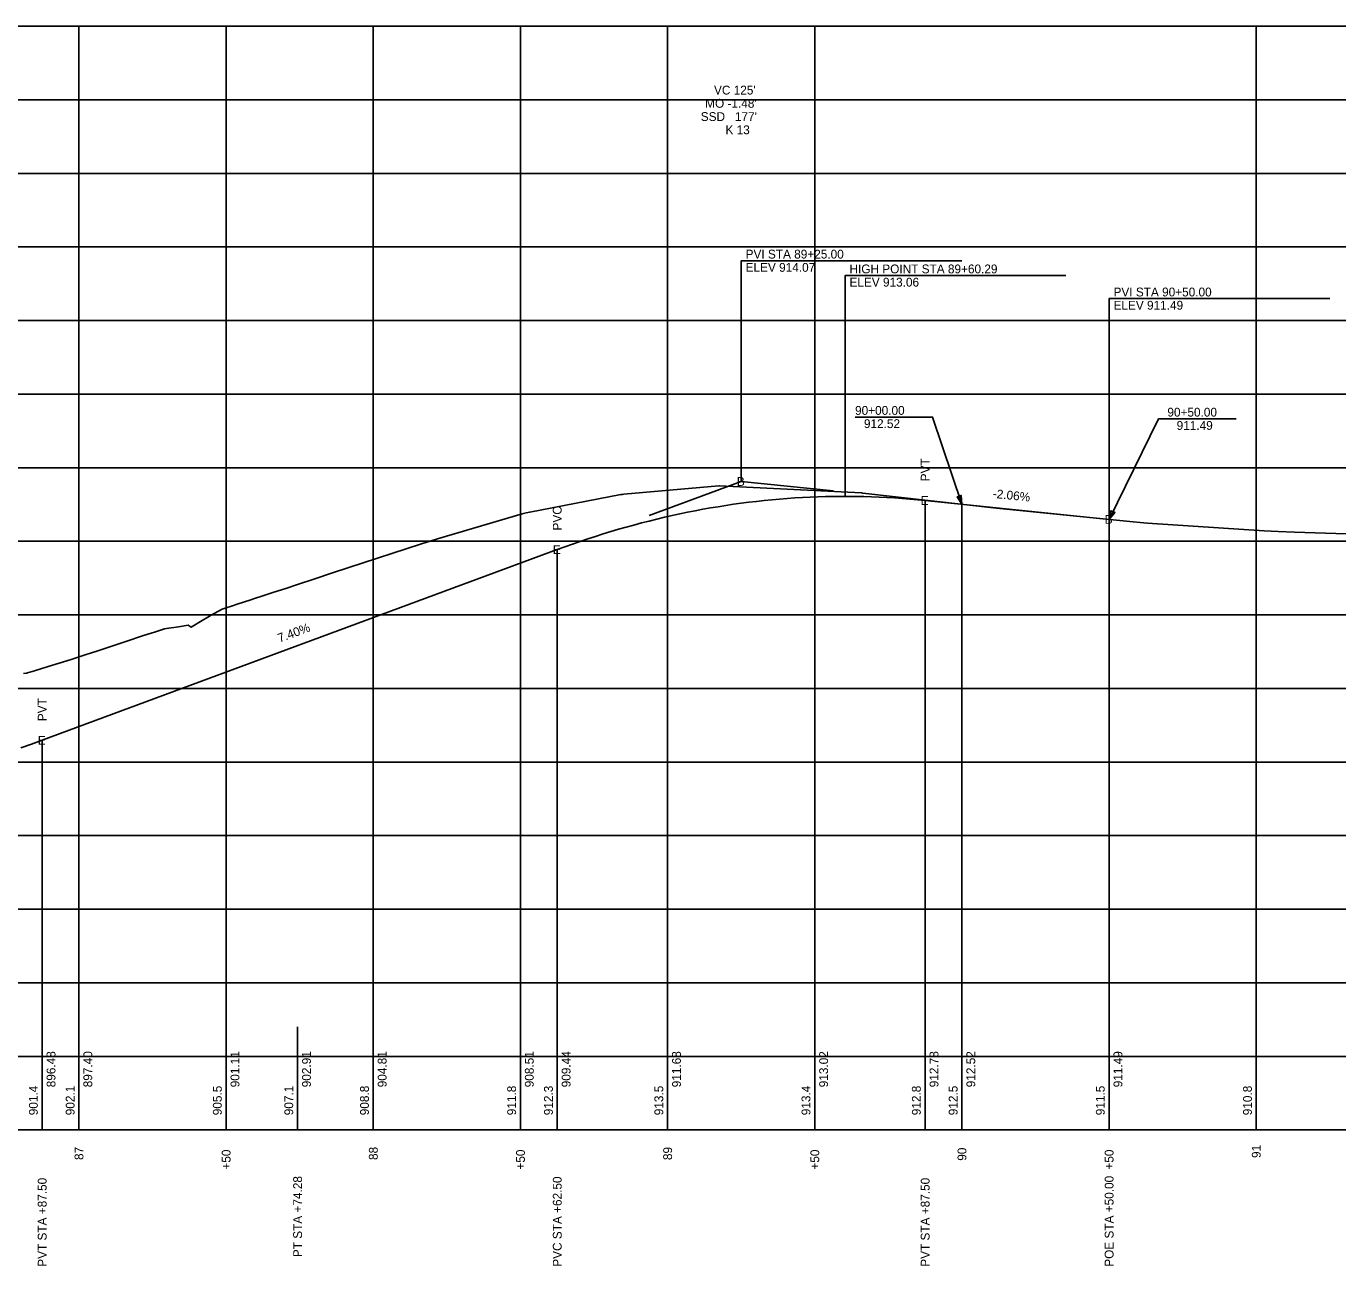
# Model space of a CAD drawing. Extents: x 76292 to 78417, y 50412 to 52585.
# Drawn here: x 77087.4 to 77533, y 51114.2 to 51535.3 of the extents above; entities that cross this region are included whole.
import ezdxf

# ---------------------------------------------------------------- set-up
doc = ezdxf.new("R2010")
doc.units = 0
for name, color, linetype in [('1', 7, 'Continuous'), ('2', 7, 'Continuous'), ('3', 7, 'Continuous'), ('32', 7, 'Continuous'), ('33', 7, 'Continuous'), ('63', 7, 'Continuous'), ('Default', 7, 'Continuous')]:
    doc.layers.add(name, color=color, linetype=linetype)

msp = doc.modelspace()

# ---------------------------------------------------------------- linework, layer by layer
at = {"layer": '1'}
for p, q in [((76305.34, 51160.35), (78405.34, 51160.35)), ((77105.34, 51160.35), (77105.34, 51160.35)), ((77155.34, 51160.35), (77155.34, 51160.35)), ((77205.34, 51160.35), (77205.34, 51160.35)), ((77255.34, 51160.35), (77255.34, 51160.35)), ((77305.34, 51160.35), (77305.34, 51160.35)), ((77355.34, 51160.35), (77355.34, 51160.35)), ((77405.34, 51160.35), (77405.34, 51160.35)), ((77455.34, 51160.35), (77455.34, 51160.35)), ((77505.34, 51160.35), (77505.34, 51160.35))]:
    msp.add_line(p, q, dxfattribs=at)
for points in [[(77330.34, 51380.67), (77330.34, 51455.67), (77405.34, 51455.67)], [(77365.63, 51375.64), (77365.63, 51450.64), (77440.63, 51450.64)], [(77455.34, 51367.8), (77455.34, 51442.8), (77530.34, 51442.8)], [(77392.84, 51374.24), (77392.84, 51160.35), (77392.84, 51160.35), (77392.84, 51160.35)], [(77455.34, 51367.8), (77455.34, 51160.35), (77455.34, 51160.35), (77455.34, 51160.35)], [(77267.84, 51357.53), (77267.84, 51160.35), (77267.84, 51160.35), (77267.84, 51160.35)], [(77092.84, 51292.74), (77092.84, 51160.35), (77092.84, 51160.35), (77092.84, 51160.35)], [(77092.84, 51160.35), (77092.84, 51195.35)], [(77092.84, 51160.35), (77092.84, 51195.35)], [(77092.84, 51160.35), (77092.84, 51195.35)], [(77092.84, 51160.35), (77092.84, 51195.35)], [(77105.34, 51160.35), (77105.34, 51195.35)], [(77105.34, 51160.35), (77105.34, 51195.35)], [(77105.34, 51160.35), (77105.34, 51195.35)], [(77105.34, 51160.35), (77105.34, 51195.35)], [(77155.34, 51160.35), (77155.34, 51195.35)], [(77155.34, 51160.35), (77155.34, 51195.35)], [(77155.34, 51160.35), (77155.34, 51195.35)], [(77155.34, 51160.35), (77155.34, 51195.35)], [(77179.62, 51160.35), (77179.62, 51195.35)], [(77179.62, 51160.35), (77179.62, 51195.35)], [(77179.62, 51160.35), (77179.62, 51195.35)], [(77179.62, 51160.35), (77179.62, 51195.35)], [(77205.34, 51160.35), (77205.34, 51195.35)], [(77205.34, 51160.35), (77205.34, 51195.35)], [(77205.34, 51160.35), (77205.34, 51195.35)], [(77205.34, 51160.35), (77205.34, 51195.35)], [(77255.34, 51160.35), (77255.34, 51195.35)], [(77255.34, 51160.35), (77255.34, 51195.35)], [(77255.34, 51160.35), (77255.34, 51195.35)], [(77255.34, 51160.35), (77255.34, 51195.35)], [(77267.84, 51160.35), (77267.84, 51195.35)], [(77267.84, 51160.35), (77267.84, 51195.35)], [(77267.84, 51160.35), (77267.84, 51195.35)], [(77267.84, 51160.35), (77267.84, 51195.35)], [(77305.34, 51160.35), (77305.34, 51195.35)], [(77305.34, 51160.35), (77305.34, 51195.35)], [(77305.34, 51160.35), (77305.34, 51195.35)], [(77305.34, 51160.35), (77305.34, 51195.35)], [(77355.34, 51160.35), (77355.34, 51195.35)], [(77355.34, 51160.35), (77355.34, 51195.35)], [(77355.34, 51160.35), (77355.34, 51195.35)], [(77355.34, 51160.35), (77355.34, 51195.35)], [(77392.84, 51160.35), (77392.84, 51195.35)], [(77392.84, 51160.35), (77392.84, 51195.35)], [(77392.84, 51160.35), (77392.84, 51195.35)], [(77392.84, 51160.35), (77392.84, 51195.35)], [(77405.34, 51160.35), (77405.34, 51195.35)], [(77405.34, 51160.35), (77405.34, 51195.35)], [(77405.34, 51160.35), (77405.34, 51195.35)], [(77405.34, 51160.35), (77405.34, 51195.35)], [(77455.34, 51160.35), (77455.34, 51195.35)], [(77455.34, 51160.35), (77455.34, 51195.35)], [(77455.34, 51160.35), (77455.34, 51195.35)], [(77455.34, 51160.35), (77455.34, 51195.35)], [(77505.34, 51160.35), (77505.34, 51195.35)], [(77505.34, 51160.35), (77505.34, 51195.35)], [(77505.34, 51160.35), (77505.34, 51195.35)], [(77505.34, 51160.35), (77505.34, 51195.35)]]:
    msp.add_lwpolyline(points, dxfattribs=at)
at = {"layer": '2'}
msp.add_lwpolyline([(77086.47, 51315.46), (77087.51, 51315.59), (77087.81, 51315.65), (77090.27, 51316.36), (77090.52, 51316.44), (77094.57, 51317.71), (77094.87, 51317.8), (77098.62, 51318.96), (77102.67, 51320.23), (77104.38, 51320.76), (77106.72, 51321.52), (77110.32, 51322.68), (77110.77, 51322.83), (77114.82, 51324.2), (77118.87, 51325.57), (77119.54, 51325.79), (77122.92, 51326.89), (77125.57, 51327.76), (77126.97, 51328.21), (77130.22, 51329.26), (77131.02, 51329.52), (77134.4, 51330.6), (77135.07, 51330.7), (77139.12, 51331.31), (77142.46, 51331.81), (77143.17, 51331.36), (77143.48, 51331.16), (77147.22, 51333.44), (77151.03, 51335.76), (77151.27, 51335.88), (77153.95, 51337.32), (77155.32, 51337.76), (77157.5, 51338.47), (77159.37, 51339.08), (77163.42, 51340.41), (77165.27, 51341.03), (77167.47, 51341.73), (77171.52, 51343.04), (77175.57, 51344.36), (77179.62, 51345.68), (77185.09, 51347.46), (77191.52, 51349.62), (77196.63, 51351.31), (77221.68, 51359.5), (77224.61, 51360.44), (77227.2, 51361.23), (77255.91, 51369.66), (77257.25, 51370.01), (77258.5, 51370.27), (77289.45, 51376.2), (77289.96, 51376.28), (77290.43, 51376.35), (77322.75, 51379.22), (77322.82, 51379.23), (77322.87, 51379.23), (77322.91, 51379.23), (77371.17, 51376.79), (77371.31, 51376.77), (77371.45, 51376.76), (77371.58, 51376.75), (77371.71, 51376.73), (77417.11, 51371.62), (77417.37, 51371.59), (77417.64, 51371.56), (77418.23, 51371.49), (77463.52, 51367), (77465.86, 51366.76), (77468.4, 51366.54), (77508.05, 51363.96), (77512.78, 51363.66), (77518.31, 51363.45), (77553.52, 51362.31)], dxfattribs=at)
at = {"layer": '32'}
for p, q in [((77392.84, 51374.24), (77455.34, 51367.8)), ((77092.84, 51292.74), (77267.84, 51357.53))]:
    msp.add_line(p, q, dxfattribs=at)
for points in [[(77299.09, 51369.1), (77330.34, 51380.67), (77361.59, 51377.45)], [(77267.84, 51357.53), (77270.44, 51358.48), (77273.05, 51359.41), (77275.65, 51360.31), (77278.26, 51361.18), (77280.86, 51362.03), (77283.46, 51362.86), (77286.07, 51363.65), (77288.67, 51364.42), (77291.28, 51365.17), (77293.88, 51365.89), (77296.49, 51366.59), (77299.09, 51367.25), (77301.69, 51367.9), (77304.3, 51368.52), (77306.9, 51369.11), (77309.51, 51369.67), (77312.11, 51370.21), (77314.71, 51370.73), (77317.32, 51371.22), (77319.92, 51371.68), (77322.53, 51372.12), (77325.13, 51372.53), (77327.74, 51372.92), (77332.94, 51373.61), (77335.55, 51373.92), (77338.15, 51374.21), (77340.76, 51374.46), (77343.36, 51374.7), (77345.96, 51374.9), (77348.57, 51375.09), (77351.17, 51375.24), (77353.78, 51375.37), (77356.38, 51375.47), (77358.99, 51375.55), (77361.59, 51375.61), (77364.19, 51375.63), (77366.8, 51375.63), (77369.4, 51375.61), (77372.01, 51375.56), (77374.61, 51375.48), (77377.21, 51375.38), (77379.82, 51375.26), (77382.42, 51375.1), (77385.03, 51374.92), (77387.63, 51374.72), (77390.24, 51374.49), (77392.84, 51374.24)], [(77085.55, 51290.16), (77089.19, 51291.42), (77092.84, 51292.74)]]:
    msp.add_lwpolyline(points, dxfattribs=at)
at = {"layer": '63'}
for p, q in [((76305.34, 51535.35), (78405.34, 51535.35)), ((76305.34, 51535.35), (78405.34, 51535.35)), ((77105.34, 51160.35), (77105.34, 51535.35)), ((77155.34, 51160.35), (77155.34, 51535.35)), ((77205.34, 51160.35), (77205.34, 51535.35)), ((77255.34, 51160.35), (77255.34, 51535.35)), ((77305.34, 51160.35), (77305.34, 51535.35)), ((77355.34, 51160.35), (77355.34, 51535.35)), ((77505.34, 51160.35), (77505.34, 51535.35)), ((76305.34, 51510.35), (78405.34, 51510.35)), ((76305.34, 51485.35), (78405.34, 51485.35)), ((76305.34, 51460.35), (78405.34, 51460.35)), ((76305.34, 51435.35), (78405.34, 51435.35)), ((76305.34, 51410.35), (78405.34, 51410.35)), ((76305.34, 51385.35), (78405.34, 51385.35)), ((77405.34, 51160.35), (77405.34, 51372.95)), ((77455.34, 51160.35), (77455.34, 51367.81)), ((76305.34, 51360.35), (78405.34, 51360.35)), ((76305.34, 51335.35), (78405.34, 51335.35)), ((76305.34, 51310.35), (78405.34, 51310.35)), ((76305.34, 51285.35), (78405.34, 51285.35)), ((76305.34, 51260.35), (78405.34, 51260.35)), ((76305.34, 51235.35), (78405.34, 51235.35)), ((76305.34, 51210.35), (78405.34, 51210.35)), ((76305.34, 51185.35), (78405.34, 51185.35))]:
    msp.add_line(p, q, dxfattribs=at)
at = {"layer": 'Default'}
for p, q in [((77369.02, 51402.57), (77392.34, 51402.57)), ((77475.14, 51401.97), (77498.45, 51401.97))]:
    msp.add_line(p, q, dxfattribs=at)
for points in [[(77405.34, 51372.95), (77395.34, 51402.57), (77392.34, 51402.57)], [(77455.34, 51367.81), (77472.14, 51401.97), (77475.14, 51401.97)]]:
    msp.add_lwpolyline(points, dxfattribs=at)
for points in [[(77405.34, 51372.95), (77403.72, 51375.47), (77405.1, 51375.94)], [(77455.34, 51367.81), (77455.97, 51370.74), (77457.28, 51370.1)]]:
    msp.add_lwpolyline(points, close=True, dxfattribs=at)

# ---------------------------------------------------------------- texts
at = {"layer": '1'}
for s, p in [('90+00.00', (77369.02, 51403.32)), ('90+50.00', (77475.14, 51402.72)), ('912.52', (77372.03, 51398.82)), ('911.49', (77478.28, 51398.22))]:
    msp.add_text(s, height=3, dxfattribs=at).set_placement(p)
for s, p in [('87', (77106.84, 51150.15)), ('+50', (77156.84, 51146.89)), ('88', (77206.84, 51150.15)), ('+50', (77256.84, 51146.89)), ('89', (77306.84, 51150.12)), ('+50', (77356.84, 51146.89)), ('90', (77406.84, 51149.89)), ('+50', (77456.84, 51146.89)), ('91', (77506.84, 51150.83))]:
    msp.add_text(s, height=3, rotation=90, dxfattribs=at).set_placement(p)
at = {"layer": '3'}
for s, p in [('901.4', (77091.34, 51165.35)), ('902.1', (77103.84, 51165.35)), ('905.5', (77153.84, 51165.35)), ('907.1', (77178.12, 51165.35)), ('908.8', (77203.84, 51165.35)), ('911.8', (77253.84, 51165.35)), ('912.3', (77266.34, 51165.35)), ('913.5', (77303.84, 51165.35)), ('913.4', (77353.84, 51165.35)), ('912.8', (77391.34, 51165.35)), ('912.5', (77403.84, 51165.35)), ('911.5', (77453.84, 51165.35)), ('910.8', (77503.84, 51165.35))]:
    msp.add_text(s, height=3, rotation=90, dxfattribs=at).set_placement(p)
at = {"layer": '33'}
for s, p in [("VC 125'", (77321.1, 51512.15)), ("MO -1.48'", (77318.1, 51507.65)), ("SSD   177'", (77316.6, 51503.15)), ('K 13', (77324.99, 51498.65)), ('B', (77328.84, 51379.17)), ('B', (77453.84, 51366.3))]:
    msp.add_text(s, height=3, dxfattribs=at).set_placement(p)
for s, rotation, p in [('PVI STA 89+25.00', 360, (77331.84, 51456.42)), ('ELEV 914.07', 360, (77331.84, 51451.92)), ('HIGH POINT STA 89+60.29', 360, (77367.13, 51451.39)), ('ELEV 913.06', 360, (77367.13, 51446.89)), ('PVI STA 90+50.00', 360, (77456.84, 51443.55)), ('ELEV 911.49', 360, (77456.84, 51439.05)), ('PVT', 90, (77394.34, 51380.74)), ('E', 360, (77391.34, 51372.74)), ('-2.06%', 354.1193, (77415.71, 51375.13)), ('PVC', 90, (77269.34, 51364.03)), ('E', 360, (77266.34, 51356.03)), ('7.40%', 20.3161, (77173.51, 51325.91)), ('PVT', 90, (77094.34, 51299.24)), ('E', 360, (77091.34, 51291.24)), ('896.48', 90, (77097.34, 51174.85)), ('897.40', 90, (77109.84, 51174.85)), ('901.11', 90, (77159.84, 51174.85)), ('902.91', 90, (77184.12, 51174.85)), ('904.81', 90, (77209.84, 51174.85)), ('908.51', 90, (77259.84, 51174.85)), ('909.44', 90, (77272.34, 51174.85)), ('911.68', 90, (77309.84, 51174.85)), ('913.02', 90, (77359.84, 51174.85)), ('912.78', 90, (77397.34, 51174.85)), ('912.52', 90, (77409.84, 51174.85)), ('911.49', 90, (77459.84, 51174.85)), ('PVT STA +87.50', 90, (77094.34, 51113.89)), ('PT STA +74.28', 90, (77181.12, 51117.15)), ('PVC STA +62.50', 90, (77269.34, 51113.89)), ('PVT STA +87.50', 90, (77394.34, 51113.89)), ('POE STA +50.00', 90, (77456.84, 51113.89))]:
    msp.add_text(s, height=3, rotation=rotation, dxfattribs=at).set_placement(p)

doc.saveas('drawing.dxf')
